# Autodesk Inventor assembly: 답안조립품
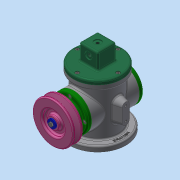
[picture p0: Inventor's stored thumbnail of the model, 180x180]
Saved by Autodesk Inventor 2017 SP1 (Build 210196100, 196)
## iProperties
Part Number: 답안조립품
Material: 일반
Document SubType Name: Assembly
Designer: MRC
Author: MRC
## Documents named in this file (18)
- C:\Users\MRC\Desktop\730206V1008\답안조립품.iam
- C:\Users\MRC\Desktop\730206V1008\본체.ipt
- C:\Users\MRC\Desktop\730206V1008\편심축.ipt
- C:\Users\MRC\Desktop\730206V1008\뒤커버.ipt
- C:\Users\MRC\Desktop\730206V1008\앞커버.ipt
- C:\Users\MRC\Desktop\730206V1008\키 4 x 4 x 12.ipt
- C:\Users\MRC\Desktop\730206V1008\덮개.ipt
- C:\Users\MRC\Desktop\730206V1008\베어링 17 x 40 x 12.ipt
- C:\Users\MRC\Desktop\730206V1008\링크.ipt
- C:\Users\MRC\Desktop\730206V1008\슬라이더.ipt
- C:\Users\MRC\Desktop\730206V1008\클레비스 핀 6 x 22.ipt
- 클레비스 핀 6 x 22.ipt
- C:\Users\MRC\Desktop\730206V1008\E-링.ipt
- C:\Users\MRC\Desktop\730206V1008\오일 실 17 30 8.ipt
- C:\Users\MRC\Desktop\730206V1008\볼트 M4 x 8.ipt
- C:\Users\MRC\Desktop\730206V1008\V-벨트풀리.ipt
- C:\Users\MRC\Desktop\730206V1008\와셔 4x16.ipt
- C:\Users\MRC\Desktop\730206V1008\볼트 M4 x 10.ipt
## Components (2 placed, 2 different names)
1. E-링:1
2. V-벨트풀리:1
